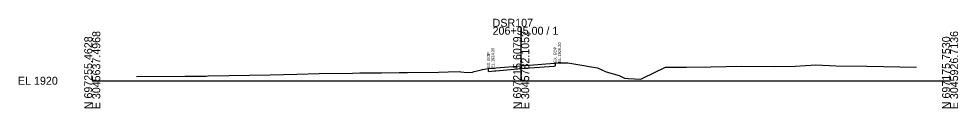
# Model space of a CAD drawing. Extents: x -26 to 19003, y -31 to 24541.
# Drawn here: x 1974.3 to 2302.8, y 16990.3 to 17021.8 of the extents above; entities that cross this region are included whole.
import ezdxf

# ---------------------------------------------------------------- set-up
doc = ezdxf.new("R2010")
doc.units = 0
for name, color, linetype in [('DESIGN - SHEET - Light Grid', 7, 'Continuous'), ('SURVEY - GROUND - Existing Pavement Layer', 7, 'Continuous'), ('SURVEY - GROUND - Existing Pavement Text', 7, 'Continuous'), ('SURVEY - GROUND - Top of Ground', 7, 'Continuous')]:
    doc.layers.add(name, color=color, linetype=linetype)

msp = doc.modelspace()

# ---------------------------------------------------------------- linework, layer by layer
at = {"layer": 'DESIGN - SHEET - Light Grid'}
for p, q in [((2150, 17000), (2150, 17018.98)), ((2000, 17000), (2150, 17000)), ((2150, 17000), (2300, 17000))]:
    msp.add_line(p, q, dxfattribs=at)
at = {"layer": 'SURVEY - GROUND - Existing Pavement Layer'}
for p, q in [((2152.87, 17004.49), (2161.58, 17005.18)), ((2161.58, 17005.18), (2161.9, 17005.2)), ((2161.9, 17006.2), (2161.9, 17005.2)), ((2138.57, 17003.3), (2138.57, 17004.3)), ((2138.57, 17003.3), (2140.73, 17003.47)), ((2140.73, 17003.47), (2141.08, 17003.54)), ((2141.08, 17003.54), (2150.07, 17004.27)), ((2150.07, 17004.27), (2152.87, 17004.49))]:
    msp.add_line(p, q, dxfattribs=at)
at = {"layer": 'SURVEY - GROUND - Top of Ground'}
msp.add_lwpolyline([(2015.52, 17001.52), (2032.53, 17001.6), (2039.88, 17001.66), (2040.58, 17001.67), (2062.24, 17002.06), (2071.5, 17002.33), (2079.35, 17002.58), (2090.99, 17002.71), (2093.57, 17002.76), (2098.47, 17002.81), (2101.19, 17002.83), (2107.32, 17002.87), (2108.95, 17002.87), (2110.25, 17002.89), (2121.07, 17003.07), (2124.41, 17003.1), (2128.48, 17003.21), (2128.84, 17003.16), (2131.12, 17002.91), (2133.01, 17003.04), (2133.6, 17003.24), (2135.69, 17003.73), (2136.44, 17003.97), (2137.06, 17004.08), (2138.57, 17004.3), (2140.73, 17004.47), (2141.08, 17004.54), (2150.07, 17005.27), (2152.87, 17005.49), (2161.58, 17006.18), (2161.9, 17006.2), (2162.84, 17006.26), (2165.67, 17006.33), (2166.37, 17006.31), (2169.1, 17005.81), (2176.7, 17004.5), (2179.72, 17003.12), (2184.22, 17001.85), (2186.19, 17000.89), (2187.44, 17000.81), (2191.89, 17000.57), (2192.55, 17000.86), (2200.44, 17004.75), (2207.76, 17004.81), (2216.35, 17004.92), (2226.98, 17005.08), (2238.48, 17004.99), (2245.78, 17005.14), (2253.04, 17005.65), (2260.12, 17005.28), (2270.94, 17005.09), (2288.3, 17004.82)], dxfattribs=at)

# ---------------------------------------------------------------- texts
at = {"layer": 'DESIGN - SHEET - Light Grid'}
for s, p in [('DSR107', (2140, 17018.98)), ('206+95.00 / 1', (2140, 17016.18)), ('EL 1920', (1974, 16998.6))]:
    msp.add_text(s, height=2.8, dxfattribs=at).set_placement(p)
for s, p in [('N 697255.4628', (2000, 16990)), ('E 3045637.4968', (2002.8, 16990)), ('N 697215.6079', (2150, 16990)), ('E 3045782.1052', (2152.8, 16990)), ('N 697175.7530', (2300, 16990)), ('E 3045926.7136', (2302.8, 16990))]:
    msp.add_text(s, height=2.8, rotation=90, dxfattribs=at).set_placement(p)
at = {"layer": 'SURVEY - GROUND - Existing Pavement Text'}
for s, p in [('EX. EOP', (2162.4, 17006.4)), ('EL.1926.20', (2163.9, 17006.4)), ('EX. EOP', (2139.07, 17004.5)), ('EL.1924.30', (2140.57, 17004.5))]:
    msp.add_text(s, height=1, rotation=90, dxfattribs=at).set_placement(p)

doc.saveas('drawing.dxf')
